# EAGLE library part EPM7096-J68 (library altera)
EPM7064 MAX 7000 family
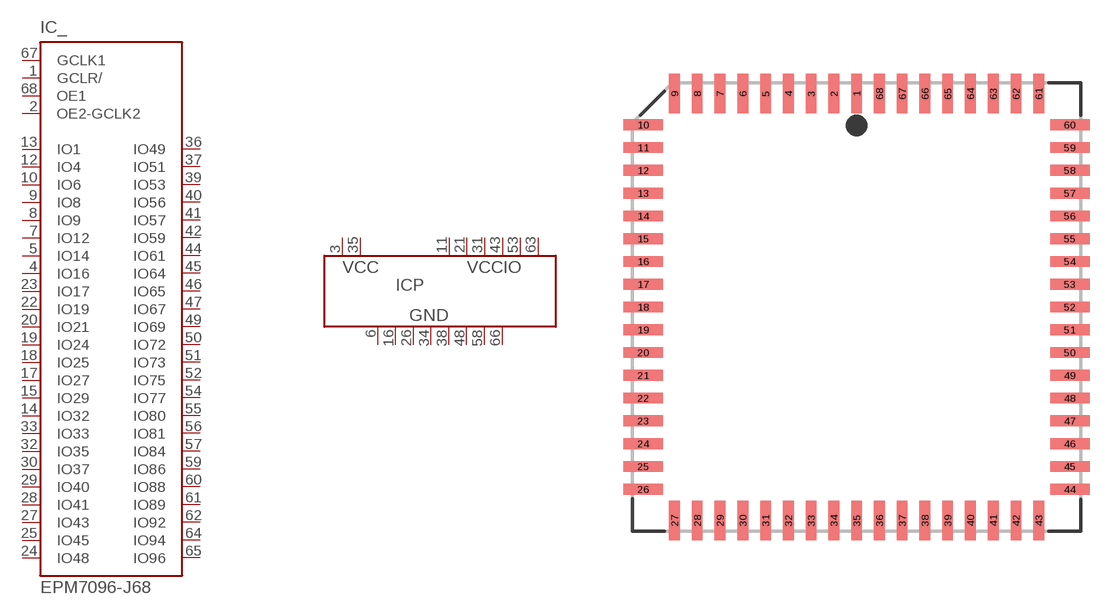
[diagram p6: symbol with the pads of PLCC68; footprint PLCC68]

Designator prefix IC; gates _=7096-68 P=PWR8-2-6

## EPM7096-J68 (MPN: EPM7096LC68-10; OC_FARNELL: unknown; OC_NEWARK: 51R9655)  [PLCC68]
1  _:GCLR/  in
2  _:OE2-GCLK2  in
3  P:VCC  pwr
4  _:IO16
5  _:IO14
6  P:GND  pwr
7  _:IO12
8  _:IO9
9  _:IO8
10  _:IO6
11  P:VCCIO  pwr
12  _:IO4
13  _:IO1
14  _:IO32
15  _:IO29
16  P:GND  pwr
17  _:IO27
18  _:IO25
19  _:IO24
20  _:IO21
21  P:VCCIO  pwr
22  _:IO19
23  _:IO17
24  _:IO48
25  _:IO45
26  P:GND  pwr
27  _:IO43
28  _:IO41
29  _:IO40
30  _:IO37
31  P:VCCIO  pwr
32  _:IO35
33  _:IO33
34  P:GND  pwr
35  P:VCC  pwr
36  _:IO49
37  _:IO51
38  P:GND  pwr
39  _:IO53
40  _:IO56
41  _:IO57
42  _:IO59
43  P:VCCIO  pwr
44  _:IO61
45  _:IO64
46  _:IO65
47  _:IO67
48  P:GND  pwr
49  _:IO69
50  _:IO72
51  _:IO73
52  _:IO75
53  P:VCCIO  pwr
54  _:IO77
55  _:IO80
56  _:IO81
57  _:IO84
58  P:GND  pwr
59  _:IO86
60  _:IO88
61  _:IO89
62  _:IO92
63  P:VCCIO  pwr
64  _:IO94
65  _:IO96
66  P:GND  pwr
67  _:GCLK1  in
68  _:OE1  in

## Footprint PLCC68 (pad centres in mm)
Plastic J-Lead Chip Carrier
smd 0.6 x 2.2: 1 0,11.9; 2 -1.27,11.9; 3 -2.54,11.9; 4 -3.81,11.9; 5 -5.08,11.9; 6 -6.35,11.9; 7 -7.62,11.9; 8 -8.89,11.9; 9 -10.16,11.9; 27 -10.16,-11.9; 28 -8.89,-11.9; 29 -7.62,-11.9; 30 -6.35,-11.9; 31 -5.08,-11.9; 32 -3.81,-11.9; 33 -2.54,-11.9; 34 -1.27,-11.9; 35 0,-11.9; 36 1.27,-11.9; 37 2.54,-11.9; 38 3.81,-11.9; 39 5.08,-11.9; 40 6.35,-11.9; 41 7.62,-11.9; 42 8.89,-11.9; 43 10.16,-11.9; 61 10.16,11.9; 62 8.89,11.9; 63 7.62,11.9; 64 6.35,11.9; 65 5.08,11.9; 66 3.81,11.9; 67 2.54,11.9; 68 1.27,11.9
smd 2.2 x 0.6: 10 -11.9,10.16; 11 -11.9,8.89; 12 -11.9,7.62; 13 -11.9,6.35; 14 -11.9,5.08; 15 -11.9,3.81; 16 -11.9,2.54; 17 -11.9,1.27; 18 -11.9,0; 19 -11.9,-1.27; 20 -11.9,-2.54; 21 -11.9,-3.81; 22 -11.9,-5.08; 23 -11.9,-6.35; 24 -11.9,-7.62; 25 -11.9,-8.89; 26 -11.9,-10.16; 44 11.9,-10.16; 45 11.9,-8.89; 46 11.9,-7.62; 47 11.9,-6.35; 48 11.9,-5.08; 49 11.9,-3.81; 50 11.9,-2.54; 51 11.9,-1.27; 52 11.9,0; 53 11.9,1.27; 54 11.9,2.54; 55 11.9,3.81; 56 11.9,5.08; 57 11.9,6.35; 58 11.9,7.62; 59 11.9,8.89; 60 11.9,10.16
